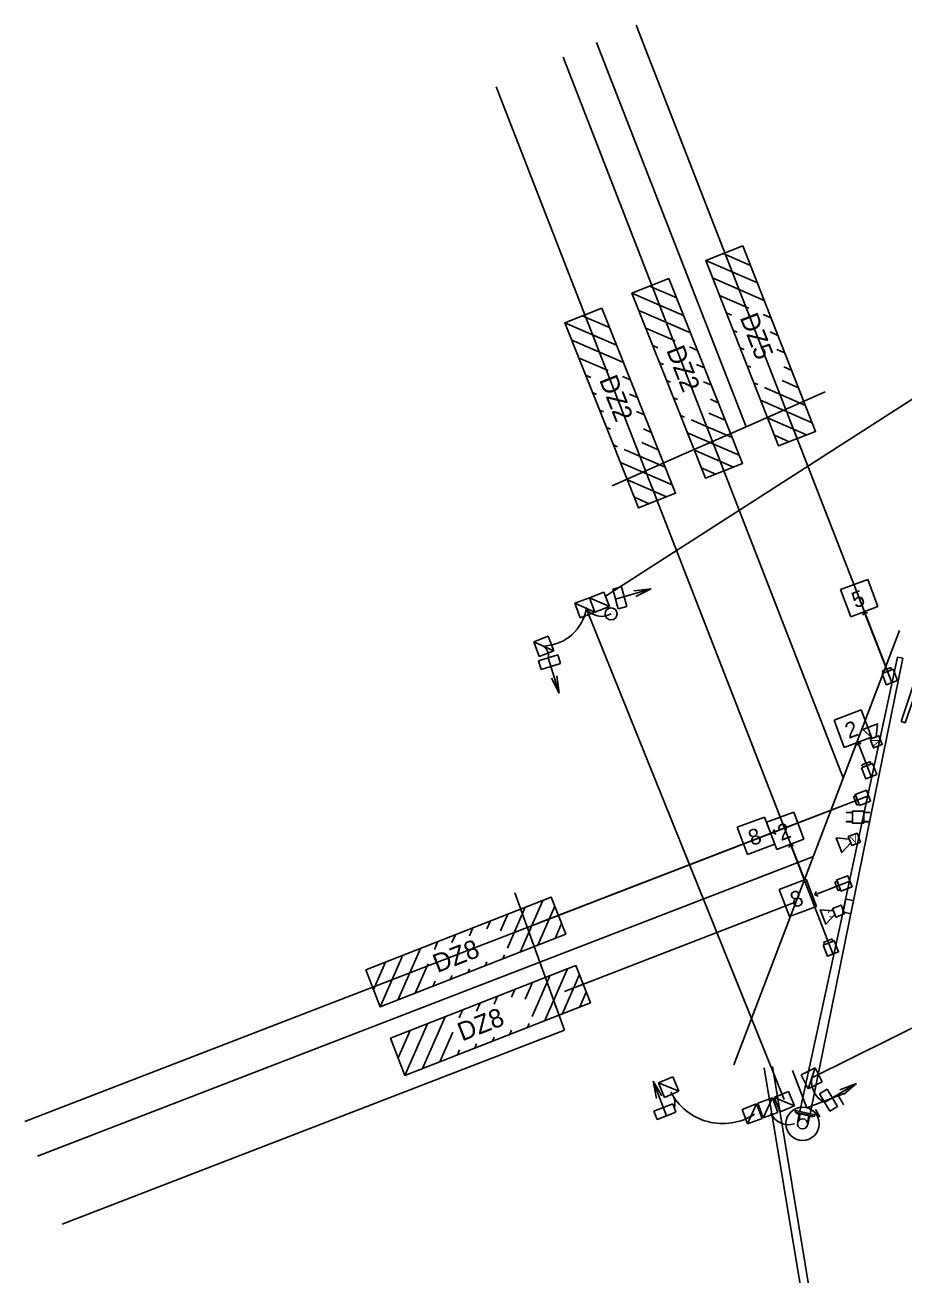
# Model space of a CAD drawing. Extents: x 510435 to 510719, y 1315254 to 1315553.
# Drawn here: x 510434.5 to 510566.8, y 1315365 to 1315553.1 of the extents above; entities that cross this region are included whole.
import ezdxf

# ---------------------------------------------------------------- set-up
doc = ezdxf.new("R2010")
doc.units = 0
for name, color, linetype in [('BankMent_ep', 7, 'Continuous'), ('Default', 7, 'Continuous'), ('DTMTriangles_ep', 7, 'Continuous'), ('FloodLight_ep', 7, 'Continuous'), ('GroundShot_ep', 7, 'Continuous'), ('TextElevLabel', 7, 'Continuous'), ('TextPtLabel', 7, 'Continuous'), ('TextSurveyLabel', 7, 'Continuous'), ('TreeLineWoods_ep', 7, 'Continuous'), ('WaterEdge_ep', 7, 'Continuous')]:
    doc.layers.add(name, color=color, linetype=linetype)

# ---------------------------------------------------------------- blocks, each defined once
blk = doc.blocks.new('VSVideoCamera')
at = {"layer": 'TextElevLabel'}
blk.add_line((0, -0.59), (0, 0.59), dxfattribs=at)
blk.add_lwpolyline([(0, 1.41), (-2.81, 1.41), (-2.81, -1.41), (0, -1.41)], close=True, dxfattribs=at)
blk.add_lwpolyline([(0, 0.59), (3.52, 2.34), (3.52, -2.34), (0, -0.59)], dxfattribs=at)
blk.add_text('V', height=2.25, dxfattribs=at).set_placement((-2.41, -1.12))
blk = doc.blocks.new('MastArmD4')
at = {"layer": 'TextSurveyLabel'}
for p, q in [((0.25, 1.5), (0, 1.5)), ((0, 1.5), (0, -1.5)), ((0, -1.04), (0, 1.04)), ((0.25, 1.5), (0.25, -1.5)), ((0.25, 0.58), (11.7, 0.52)), ((9.7, 0.54), (46, 0.33)), ((9.7, 0.54), (9.7, -0.54)), ((11.7, 0.52), (11.7, -0.52)), ((46, 0.33), (46, -0.33)), ((0.25, -1.5), (0, -1.5)), ((0.25, -0.58), (11.7, -0.52)), ((9.7, -0.54), (46, -0.33))]:
    blk.add_line(p, q, dxfattribs=at)

msp = doc.modelspace()

# ---------------------------------------------------------------- linework, layer by layer
at = {"layer": 'BankMent_ep'}
for p, q in [((510559.14, 1315434.57), (510558.24, 1315434.51)), ((510558.24, 1315434.51), (510558.24, 1315434.48)), ((510560.84, 1315434.57), (510561.74, 1315434.51)), ((510561.74, 1315434.51), (510561.74, 1315434.48)), ((510558.24, 1315434.48), (510559.14, 1315434.48)), ((510558.24, 1315433.12), (510558.24, 1315433.15)), ((510558.24, 1315433.15), (510559.14, 1315433.15)), ((510559.14, 1315433.06), (510558.24, 1315433.12)), ((510561.74, 1315434.48), (510560.84, 1315434.48)), ((510561.74, 1315433.15), (510560.84, 1315433.15)), ((510560.84, 1315433.06), (510561.74, 1315433.12)), ((510561.74, 1315433.12), (510561.74, 1315433.15))]:
    msp.add_line(p, q, dxfattribs=at)
for points in [[(510559.14, 1315434.48), (510558.24, 1315434.48), (510558.24, 1315434.51), (510559.14, 1315434.57)], [(510560.84, 1315434.71), (510560.84, 1315432.92), (510559.14, 1315432.92), (510559.14, 1315434.71)], [(510560.84, 1315432.92), (510559.14, 1315432.92), (510559.14, 1315434.71), (510560.84, 1315434.71)], [(510560.84, 1315434.48), (510561.74, 1315434.48), (510561.74, 1315434.51), (510560.84, 1315434.57)], [(510559.14, 1315433.06), (510558.24, 1315433.12), (510558.24, 1315433.15), (510559.14, 1315433.15)], [(510560.84, 1315433.06), (510561.74, 1315433.12), (510561.74, 1315433.15), (510560.84, 1315433.15)]]:
    msp.add_lwpolyline(points, close=True, dxfattribs=at)
at = {"layer": 'Default'}
for p, q in [((510537.05, 1315517.61), (510544.82, 1315514.22)), ((510539.68, 1315518.64), (510543.79, 1315516.85)), ((510528.56, 1315513.73), (510532.68, 1315511.96)), ((510538.08, 1315514.98), (510545.86, 1315511.59)), ((510525.93, 1315512.69), (510533.72, 1315509.33)), ((510539.11, 1315512.35), (510543.54, 1315510.41)), ((510526.97, 1315510.06), (510534.76, 1315506.7)), ((510540.15, 1315509.71), (510540.91, 1315509.38)), ((510515.82, 1315508.22), (510523.61, 1315504.87)), ((510518.44, 1315509.27), (510522.57, 1315507.5)), ((510545.7, 1315509.47), (510546.89, 1315508.95)), ((510528.02, 1315507.43), (510532.46, 1315505.52)), ((510541.18, 1315507.08), (510541.78, 1315506.82)), ((510546.73, 1315506.84), (510547.92, 1315506.32)), ((510516.87, 1315505.59), (510524.66, 1315502.24)), ((510529.06, 1315504.8), (510529.83, 1315504.47)), ((510534.62, 1315504.59), (510535.81, 1315504.07)), ((510542.21, 1315504.45), (510542.81, 1315504.19)), ((510547.77, 1315504.21), (510548.96, 1315503.69)), ((510517.91, 1315502.96), (510522.35, 1315501.06)), ((510518.96, 1315500.34), (510519.73, 1315500.01)), ((510530.11, 1315502.18), (510530.71, 1315501.92)), ((510535.66, 1315501.96), (510536.85, 1315501.44)), ((510543.25, 1315501.81), (510543.85, 1315501.55)), ((510548.8, 1315501.57), (510549.99, 1315501.05)), ((510524.52, 1315500.13), (510525.71, 1315499.62)), ((510531.15, 1315499.55), (510531.75, 1315499.29)), ((510536.71, 1315499.33), (510537.9, 1315498.81)), ((510544.28, 1315499.18), (510544.88, 1315498.92)), ((510545.91, 1315498.47), (510552.06, 1315495.79)), ((510548.54, 1315499.51), (510551.02, 1315498.42)), ((510520.01, 1315497.71), (510520.61, 1315497.45)), ((510525.57, 1315497.5), (510526.76, 1315496.99)), ((510532.19, 1315496.92), (510532.79, 1315496.66)), ((510537.75, 1315496.7), (510538.94, 1315496.19)), ((510521.06, 1315495.08), (510521.66, 1315494.83)), ((510526.61, 1315494.87), (510527.81, 1315494.36)), ((510545.31, 1315496.55), (510553.09, 1315493.16)), ((510533.24, 1315494.29), (510533.84, 1315494.03)), ((510534.87, 1315493.59), (510541.03, 1315490.93)), ((510537.5, 1315494.63), (510539.99, 1315493.56)), ((510546.35, 1315493.92), (510552.24, 1315491.35)), ((510522.11, 1315492.46), (510522.71, 1315492.2)), ((510527.66, 1315492.25), (510528.85, 1315491.73)), ((510534.28, 1315491.66), (510542.07, 1315488.3)), ((510547.38, 1315491.28), (510549.6, 1315490.31)), ((510523.15, 1315489.83), (510523.75, 1315489.57)), ((510524.78, 1315489.13), (510530.95, 1315486.48)), ((510527.41, 1315490.18), (510529.9, 1315489.11)), ((510535.33, 1315489.03), (510541.22, 1315486.49)), ((510524.2, 1315487.2), (510532, 1315483.85)), ((510536.37, 1315486.4), (510538.59, 1315485.44)), ((510525.25, 1315484.58), (510531.15, 1315482.04)), ((510526.3, 1315481.95), (510528.52, 1315480.99)), ((510512.06, 1315417.93), (510549.38, 1315432.34)), ((510507.19, 1315414.08), (510509.87, 1315420.23)), ((510509.11, 1315413.49), (510512.51, 1315421.26)), ((510511.74, 1315414.52), (510514.32, 1315420.4)), ((510504.09, 1315416.98), (510504.61, 1315418.17)), ((510506.15, 1315416.71), (510507.24, 1315419.2)), ((510514.38, 1315415.55), (510515.35, 1315417.77)), ((510498.82, 1315414.91), (510499.34, 1315416.1)), ((510501.45, 1315415.95), (510501.97, 1315417.14)), ((510490.67, 1315406.27), (510494.07, 1315414.04)), ((510496.19, 1315413.88), (510496.71, 1315415.07)), ((510487.01, 1315407.87), (510488.81, 1315411.98)), ((510488.04, 1315405.23), (510491.44, 1315413.01)), ((510503.84, 1315411.42), (510504.1, 1315412.02)), ((510506.48, 1315412.46), (510506.74, 1315413.05)), ((510493.31, 1315407.3), (510495.24, 1315411.73)), ((510501.21, 1315410.39), (510501.47, 1315410.99)), ((510512.83, 1315403.18), (510516.23, 1315410.96)), ((510515.46, 1315404.22), (510518.03, 1315410.1)), ((510495.94, 1315408.33), (510496.28, 1315409.09)), ((510498.58, 1315409.36), (510498.84, 1315409.96)), ((510509.87, 1315406.41), (510510.96, 1315408.9)), ((510510.9, 1315403.78), (510513.59, 1315409.93)), ((510505.17, 1315405.64), (510505.69, 1315406.83)), ((510507.8, 1315406.68), (510508.32, 1315407.86)), ((510518.09, 1315405.25), (510519.06, 1315407.47)), ((510499.9, 1315403.58), (510500.42, 1315404.77)), ((510502.54, 1315404.61), (510503.06, 1315405.8)), ((510491.76, 1315394.93), (510495.16, 1315402.71)), ((510494.39, 1315395.96), (510497.79, 1315403.74)), ((510510.19, 1315402.15), (510510.46, 1315402.75)), ((510490.73, 1315397.56), (510492.52, 1315401.67)), ((510497.03, 1315396.99), (510498.96, 1315401.42)), ((510504.93, 1315400.09), (510505.19, 1315400.69)), ((510507.56, 1315401.12), (510507.82, 1315401.72)), ((510499.66, 1315398.03), (510499.99, 1315398.79)), ((510502.29, 1315399.06), (510502.55, 1315399.66))]:
    msp.add_line(p, q, dxfattribs=at)
for points in [[(510542.63, 1315519.8), (510553.59, 1315491.88), (510548.01, 1315489.69), (510537.05, 1315517.61)], [(510531.51, 1315514.91), (510542.58, 1315487.03), (510537, 1315484.81), (510525.93, 1315512.69)], [(510521.39, 1315510.44), (510532.51, 1315482.58), (510526.93, 1315480.36), (510515.82, 1315508.22)], [(510485.85, 1315410.82), (510513.78, 1315421.76), (510515.97, 1315416.18), (510488.04, 1315405.23)], [(510489.57, 1315400.52), (510517.5, 1315411.46), (510519.69, 1315405.87), (510491.76, 1315394.93)]]:
    msp.add_lwpolyline(points, close=True, dxfattribs=at)
for centre, radius, start, end in [((510512.38, 1315466.33), 6.78, 273.1372, 350.3528), ((510521.37, 1315466.86), 2.84, 215.0224, 300.6598), ((510511.67, 1315458.13), 1.69, 347.7038, 57.3021), ((510556.51, 1315394.03), 3.54, 171.6762, 243.7101), ((510529.49, 1315390.66), 2.9, 347.5163, 37.787), ((510539.6, 1315396.46), 8.79, 207.216, 303.1115), ((510549.52, 1315390.41), 2.91, 202.1814, 287.6769)]:
    msp.add_arc(centre, radius, start, end, dxfattribs=at)
at = {"layer": 'DTMTriangles_ep'}
msp.add_circle((510522.8, 1315464.4), 0.9, dxfattribs=at)
at = {"layer": 'FloodLight_ep'}
for q in [(510550.12, 1315395.65), (510557.88, 1315392.21)]:
    msp.add_line((510552.28, 1315390.05), q, dxfattribs=at)
at = {"layer": 'GroundShot_ep'}
for p, q in [((510517.33, 1315466.01), (510519.52, 1315466.84)), ((510519.52, 1315466.84), (510521.71, 1315467.68)), ((510520.35, 1315464.65), (510519.52, 1315466.84)), ((510522.54, 1315465.49), (510519.52, 1315466.84)), ((510519.52, 1315466.84), (510520.35, 1315464.65)), ((510521.71, 1315467.68), (510522.54, 1315465.49)), ((510518.16, 1315463.82), (510517.33, 1315466.01)), ((510520.35, 1315464.65), (510517.33, 1315466.01)), ((510520.35, 1315464.65), (510518.16, 1315463.82)), ((510522.54, 1315465.49), (510520.35, 1315464.65)), ((510511.15, 1315460.2), (510513.34, 1315461.03)), ((510513.34, 1315461.03), (510514.17, 1315458.84)), ((510511.98, 1315458.01), (510511.15, 1315460.2)), ((510514.17, 1315458.84), (510511.15, 1315460.2)), ((510514.17, 1315458.84), (510511.98, 1315458.01)), ((510551.41, 1315394.99), (510553.5, 1315396.05)), ((510552.47, 1315392.9), (510553.5, 1315396.05)), ((510553.5, 1315396.05), (510554.56, 1315393.96)), ((510529.95, 1315393.79), (510532.11, 1315394.69)), ((510530.85, 1315391.62), (510529.95, 1315393.79)), ((510529.95, 1315393.79), (510533.01, 1315392.53)), ((510532.11, 1315394.69), (510533.01, 1315392.53)), ((510552.47, 1315392.9), (510551.41, 1315394.99)), ((510554.56, 1315393.96), (510552.47, 1315392.9)), ((510533.01, 1315392.53), (510530.85, 1315391.62)), ((510544.88, 1315390.73), (510547.08, 1315391.55)), ((510545.7, 1315388.53), (510547.08, 1315391.55)), ((510547.08, 1315391.55), (510547.9, 1315389.35)), ((510547.34, 1315391.61), (510549.5, 1315392.51)), ((510548.24, 1315389.45), (510547.34, 1315391.61)), ((510547.34, 1315391.61), (510550.4, 1315390.35)), ((510549.5, 1315392.51), (510550.4, 1315390.35)), ((510542.51, 1315389.81), (510544.71, 1315390.63)), ((510543.33, 1315387.61), (510542.51, 1315389.81)), ((510543.33, 1315387.61), (510544.71, 1315390.63)), ((510544.71, 1315390.63), (510545.53, 1315388.43)), ((510545.7, 1315388.53), (510544.88, 1315390.73)), ((510550.4, 1315390.35), (510548.24, 1315389.45)), ((510545.53, 1315388.43), (510543.33, 1315387.61)), ((510547.9, 1315389.35), (510545.7, 1315388.53))]:
    msp.add_line(p, q, dxfattribs=at)
at = {"layer": 'TextElevLabel'}
msp.add_line((510556.47, 1315419.14), (510556.26, 1315419.68), dxfattribs=at)
msp.add_lwpolyline([(510556.26, 1315419.68), (510554.3, 1315419.87), (510555.14, 1315417.68), (510556.47, 1315419.14)], dxfattribs=at)
msp.add_lwpolyline([(510556.11, 1315420.07), (510557.42, 1315420.57), (510557.93, 1315419.26), (510556.62, 1315418.76)], close=True, dxfattribs=at)
msp.add_circle((510551.63, 1315387.64), 2.5, dxfattribs=at)
at = {"layer": 'TextPtLabel'}
for p, q in [((510521.96, 1315467.05), (510573.34, 1315500.1)), ((510548.84, 1315391.28), (510519.01, 1315465.38)), ((510553, 1315394.55), (510617.23, 1315426.44))]:
    msp.add_line(p, q, dxfattribs=at)
at = {"layer": 'TextSurveyLabel'}
for p, q in [((510560.7, 1315464.23), (510560.92, 1315464.73)), ((510565.07, 1315454.07), (510560.92, 1315464.73)), ((510561.41, 1315464.51), (510560.92, 1315464.73)), ((510557.68, 1315419.53), (510565.94, 1315457.91)), ((510566.71, 1315457.75), (510558.9, 1315419.27)), ((510566.71, 1315457.75), (510565.94, 1315457.91)), ((510564.83, 1315456.3), (510563.74, 1315455.87)), ((510564.83, 1315456.3), (510563.74, 1315455.87)), ((510564.96, 1315455.95), (510563.87, 1315455.52)), ((510559.74, 1315444.58), (510559.96, 1315445.07)), ((510561.97, 1315439.91), (510559.96, 1315445.07)), ((510560.45, 1315444.86), (510559.96, 1315445.07)), ((510561.73, 1315442.14), (510560.64, 1315441.71)), ((510561.73, 1315442.14), (510560.64, 1315441.71)), ((510561.87, 1315441.79), (510560.78, 1315441.36)), ((510561.56, 1315437.03), (510547.17, 1315431.47)), ((510559.33, 1315436.79), (510559.75, 1315435.7)), ((510559.33, 1315436.79), (510559.75, 1315435.7)), ((510559.68, 1315436.93), (510560.1, 1315435.84)), ((510547.39, 1315431.96), (510547.17, 1315431.47)), ((510547.66, 1315431.25), (510547.17, 1315431.47)), ((510549.57, 1315429.22), (510549.79, 1315429.71)), ((510556.2, 1315413.22), (510549.79, 1315429.71)), ((510550.28, 1315429.49), (510549.79, 1315429.71)), ((510558.76, 1315424.16), (510553.46, 1315422.11)), ((510556.53, 1315423.92), (510556.95, 1315422.83)), ((510556.53, 1315423.92), (510556.95, 1315422.83)), ((510556.88, 1315424.06), (510557.3, 1315422.97)), ((510551.23, 1315389.47), (510558.12, 1315421.47)), ((510553.68, 1315422.6), (510553.46, 1315422.11)), ((510553.95, 1315421.89), (510553.46, 1315422.11)), ((510559.28, 1315421.23), (510558.12, 1315421.47)), ((510559.28, 1315421.23), (510552.77, 1315389.15)), ((510557.68, 1315419.53), (510558.9, 1315419.27)), ((510555.97, 1315415.43), (510554.88, 1315415)), ((510555.97, 1315415.43), (510554.88, 1315415)), ((510556.11, 1315415.08), (510555.02, 1315414.65)), ((510550.49, 1315389.37), (510550.54, 1315389.62)), ((510553.46, 1315389), (510550.54, 1315389.62)), ((510553.41, 1315388.76), (510550.49, 1315389.37)), ((510550.72, 1315389.17), (510550.75, 1315389.32)), ((510550.72, 1315389.17), (510551.25, 1315389.06)), ((510550.75, 1315389.32), (510553.11, 1315388.82)), ((510550.86, 1315387.8), (510551.12, 1315389.08)), ((510550.86, 1315387.8), (510550.9, 1315387.79)), ((510550.9, 1315387.79), (510551.17, 1315389.07)), ((510551.05, 1315388.11), (510551.26, 1315389.13)), ((510551.26, 1315389.13), (510552.57, 1315388.86)), ((510552.35, 1315387.84), (510552.57, 1315388.86)), ((510552.36, 1315387.48), (510552.63, 1315388.77)), ((510552.41, 1315387.47), (510552.67, 1315388.76)), ((510552.55, 1315388.78), (510553.08, 1315388.67)), ((510553.08, 1315388.67), (510553.11, 1315388.82)), ((510553.41, 1315388.76), (510553.46, 1315389)), ((510552.41, 1315387.47), (510552.36, 1315387.48))]:
    msp.add_line(p, q, dxfattribs=at)
for points in [[(510563.59, 1315455.41), (510565.25, 1315456.06), (510565.9, 1315454.39), (510564.23, 1315453.74)], [(510560.49, 1315441.25), (510562.15, 1315441.9), (510562.8, 1315440.23), (510561.14, 1315439.58)], [(510560.21, 1315435.55), (510559.57, 1315437.22), (510561.23, 1315437.86), (510561.88, 1315436.19)], [(510557.41, 1315422.68), (510556.77, 1315424.35), (510558.44, 1315424.99), (510559.08, 1315423.32)], [(510554.73, 1315414.54), (510556.4, 1315415.19), (510557.04, 1315413.52), (510555.38, 1315412.88)], [(510551.59, 1315388.41), (510551.98, 1315388.33), (510552.28, 1315388.06), (510552.41, 1315387.68), (510552.32, 1315387.29), (510552.06, 1315386.99), (510551.67, 1315386.86), (510551.28, 1315386.94), (510550.98, 1315387.21), (510550.86, 1315387.59), (510550.94, 1315387.99), (510551.21, 1315388.29)]]:
    msp.add_lwpolyline(points, close=True, dxfattribs=at)
for points in [[(510563.87, 1315455.52), (510564.96, 1315455.95)], [(510560.78, 1315441.36), (510561.87, 1315441.79)], [(510560.1, 1315435.84), (510559.68, 1315436.93)], [(510557.3, 1315422.97), (510556.88, 1315424.06)], [(510555.02, 1315414.65), (510556.11, 1315415.08)]]:
    msp.add_lwpolyline(points, dxfattribs=at)
for centre, radius, start, end in [((510563.78, 1315455.76), 0.115, 111.2547, 230.5746), ((510563.78, 1315455.76), 0.115, 111.2547, 230.5745), ((510562.34, 1315454.02), 2.14, 44.4713, 50.5746), ((510562.34, 1315454.02), 2.14, 44.4713, 50.5746), ((510564.87, 1315456.19), 0.115, 351.9349, 111.2547), ((510564.87, 1315456.19), 0.115, 351.9349, 111.2547), ((510567.11, 1315455.87), 2.14, 171.9349, 178.0381), ((510567.11, 1315455.87), 2.14, 171.9349, 178.0381), ((510561.77, 1315442.03), 0.115, 351.9349, 111.2547), ((510561.77, 1315442.03), 0.115, 351.9349, 111.2547), ((510560.68, 1315441.6), 0.115, 111.2547, 230.5746), ((510560.68, 1315441.6), 0.115, 111.2547, 230.5745), ((510559.25, 1315439.86), 2.14, 44.4713, 50.5746), ((510559.25, 1315439.86), 2.14, 44.4713, 50.5746), ((510564.01, 1315441.71), 2.14, 171.9349, 178.0381), ((510564.01, 1315441.71), 2.14, 171.9349, 178.0381), ((510559.43, 1315436.84), 0.115, 81.8013, 201.1211), ((510559.43, 1315436.84), 0.115, 81.8013, 201.1211), ((510559.76, 1315439.07), 2.14, 261.8013, 267.9046), ((510559.76, 1315439.07), 2.14, 261.8013, 267.9046), ((510559.86, 1315435.74), 0.115, 201.1211, 320.441), ((510559.86, 1315435.74), 0.115, 201.1211, 320.4409), ((510561.6, 1315434.3), 2.14, 134.3377, 140.441), ((510561.6, 1315434.3), 2.14, 134.3377, 140.441), ((510556.64, 1315423.97), 0.115, 81.8013, 201.1211), ((510556.64, 1315423.97), 0.115, 81.8013, 201.1211), ((510556.96, 1315426.2), 2.14, 261.8013, 267.9046), ((510556.96, 1315426.2), 2.14, 261.8013, 267.9046), ((510557.06, 1315422.87), 0.115, 201.1211, 320.441), ((510557.06, 1315422.87), 0.115, 201.1211, 320.4409), ((510558.8, 1315421.43), 2.14, 134.3377, 140.441), ((510558.8, 1315421.43), 2.14, 134.3377, 140.441), ((510554.92, 1315414.9), 0.115, 111.2547, 230.5746), ((510554.92, 1315414.9), 0.115, 111.2547, 230.5745), ((510553.49, 1315413.15), 2.14, 44.4713, 50.5746), ((510553.49, 1315413.15), 2.14, 44.4713, 50.5746), ((510556.01, 1315415.32), 0.115, 351.9349, 111.2547), ((510556.01, 1315415.32), 0.115, 351.9349, 111.2547), ((510558.25, 1315415), 2.14, 171.9349, 178.0381), ((510558.25, 1315415), 2.14, 171.9349, 178.0381)]:
    msp.add_arc(centre, radius, start, end, dxfattribs=at)
at = {"layer": 'TreeLineWoods_ep'}
for p, q in [((510564.15, 1315456.47), (510526.58, 1315553.05)), ((510543.12, 1315492.58), (510520.62, 1315550.42)), ((510557.76, 1315439.72), (510515.57, 1315548.19)), ((510551.92, 1315424.4), (510505.5, 1315543.74)), ((510543.12, 1315492.58), (510555.03, 1315497.85)), ((510543.12, 1315492.58), (510555.03, 1315497.85)), ((510549.71, 1315493.58), (510550.8, 1315490.78)), ((510533.01, 1315488.12), (510543.12, 1315492.58)), ((510533.01, 1315488.12), (510522.98, 1315483.68)), ((510538.7, 1315488.71), (510539.79, 1315485.92)), ((510528.63, 1315484.26), (510529.36, 1315482.4)), ((510528.63, 1315484.26), (510529.72, 1315481.47)), ((510541.28, 1315396.51), (510566.23, 1315461.92)), ((510541.28, 1315396.51), (510562.66, 1315452.57)), ((510555.91, 1315434.86), (510434.54, 1315387.98)), ((510553.25, 1315427.89), (510436.42, 1315382.76)), ((510512.08, 1315411.99), (510508.31, 1315422.42)), ((510515.8, 1315407.58), (510550.64, 1315421.04)), ((510512.06, 1315417.93), (510514.86, 1315419.01)), ((510515.78, 1315401.74), (510512.08, 1315411.99)), ((510515.8, 1315407.58), (510518.6, 1315408.67)), ((510515.78, 1315401.74), (510440.12, 1315372.52)), ((510568.82, 1315257.9), (510545.86, 1315396.08)), ((510570.06, 1315258.1), (510547.09, 1315396.28))]:
    msp.add_line(p, q, dxfattribs=at)
for points in [[(510557.8, 1315390.5), (510557.59, 1315390.9), (510556.97, 1315391.9)], [(510554.22, 1315388.7), (510554.1, 1315388.94), (510553.58, 1315389.78)]]:
    msp.add_lwpolyline(points, dxfattribs=at)
at = {"layer": 'WaterEdge_ep'}
for p, q in [((510523.05, 1315468.1), (510524.34, 1315468.46)), ((510524.34, 1315468.46), (510525.17, 1315465.53)), ((510557.34, 1315468.05), (510561.43, 1315469.59)), ((510561.43, 1315469.59), (510562.97, 1315465.49)), ((510523.88, 1315465.16), (510523.05, 1315468.1)), ((510523.46, 1315466.63), (510528.82, 1315468.15)), ((510528.82, 1315468.15), (510526.2, 1315467.88)), ((510528.82, 1315468.15), (510526.51, 1315467.03)), ((510557.34, 1315468.05), (510558.87, 1315463.96)), ((510525.17, 1315465.53), (510523.88, 1315465.16)), ((510558.87, 1315463.96), (510562.97, 1315465.49)), ((510511.87, 1315457.32), (510514.78, 1315458.22)), ((510512.26, 1315456.04), (510511.87, 1315457.32)), ((510513.32, 1315457.77), (510514.97, 1315452.45)), ((510514.78, 1315458.22), (510515.17, 1315456.94)), ((510515.17, 1315456.94), (510512.26, 1315456.04)), ((510514.97, 1315452.45), (510513.8, 1315454.73)), ((510514.97, 1315452.45), (510514.64, 1315455.07)), ((510556.37, 1315448.4), (510560.47, 1315449.94)), ((510560.47, 1315449.94), (510562.01, 1315445.84)), ((510556.37, 1315448.4), (510557.91, 1315444.31)), ((510557.91, 1315444.31), (510562.01, 1315445.84)), ((510546.2, 1315433.04), (510550.3, 1315434.57)), ((510550.3, 1315434.57), (510551.84, 1315430.48)), ((510541.8, 1315432.28), (510545.89, 1315433.82)), ((510545.89, 1315433.82), (510547.43, 1315429.72)), ((510546.2, 1315433.04), (510547.74, 1315428.94)), ((510541.8, 1315432.28), (510543.33, 1315428.19)), ((510543.33, 1315428.19), (510547.43, 1315429.72)), ((510547.74, 1315428.94), (510551.84, 1315430.48)), ((510548.1, 1315422.93), (510552.19, 1315424.47)), ((510552.19, 1315424.47), (510553.73, 1315420.37)), ((510548.1, 1315422.93), (510549.64, 1315418.83)), ((510549.64, 1315418.83), (510553.73, 1315420.37)), ((510529.11, 1315394.04), (510530.45, 1315391.85)), ((510531.14, 1315388.85), (510529.11, 1315394.04)), ((510529.11, 1315394.04), (510529.63, 1315391.45)), ((510554.94, 1315390.86), (510559.73, 1315393.71)), ((510559.73, 1315393.71), (510557.26, 1315392.77)), ((510559.73, 1315393.71), (510557.78, 1315392.03)), ((510554.16, 1315392.17), (510555.31, 1315392.86)), ((510555.72, 1315389.55), (510554.16, 1315392.17)), ((510555.31, 1315392.86), (510556.87, 1315390.24)), ((510529.24, 1315389.55), (510532.07, 1315390.66)), ((510529.73, 1315388.3), (510529.24, 1315389.55)), ((510532.56, 1315389.41), (510529.73, 1315388.3)), ((510532.07, 1315390.66), (510532.56, 1315389.41)), ((510556.87, 1315390.24), (510555.72, 1315389.55))]:
    msp.add_line(p, q, dxfattribs=at)

# ---------------------------------------------------------------- block references
at = {"layer": 'TextSurveyLabel'}
for name, p, xscale, yscale, rotation in [('MastArmD4', (510582.8, 1315495.74), 1.0928961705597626, 0.9999999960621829, -108.57724603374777), ('VSVideoCamera', (510562.45, 1315445.8), 0.5, 0.5, 111.1211376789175), ('VSVideoCamera', (510558.77, 1315430.21), 0.4999999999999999, -0.5, -158.8788567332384)]:
    msp.add_blockref(name, p, dxfattribs=dict(at, xscale=xscale, yscale=yscale, rotation=rotation))

# ---------------------------------------------------------------- texts
at = {"layer": 'Default'}
for s, rotation, p in [('DZ5 ', 291.4329, (510542.14, 1315509.01)), ('DZ2 ', 291.6617, (510531.06, 1315504.11)), ('DZ2 ', 291.7504, (510520.96, 1315499.65)), ('DZ8 ', 21.3911, (510496.64, 1315410.32)), ('DZ8 ', 21.3911, (510500.36, 1315400.02))]:
    msp.add_text(s, height=2.8, rotation=rotation, dxfattribs=at).set_placement(p)
at = {"layer": 'TextElevLabel'}
msp.add_text('C', height=1.12, rotation=201.1211, dxfattribs=at).set_placement((510556.3, 1315420.02))
at = {"layer": 'WaterEdge_ep'}
for s, p in [('5', (510559.57, 1315465.21)), ('2', (510558.57, 1315445.55)), ('2', (510548.4, 1315430.19)), ('8', (510544, 1315429.43)), ('8', (510550.31, 1315420.08))]:
    msp.add_text(s, height=2.4, rotation=20.582, dxfattribs=at).set_placement(p)

doc.saveas('drawing.dxf')
